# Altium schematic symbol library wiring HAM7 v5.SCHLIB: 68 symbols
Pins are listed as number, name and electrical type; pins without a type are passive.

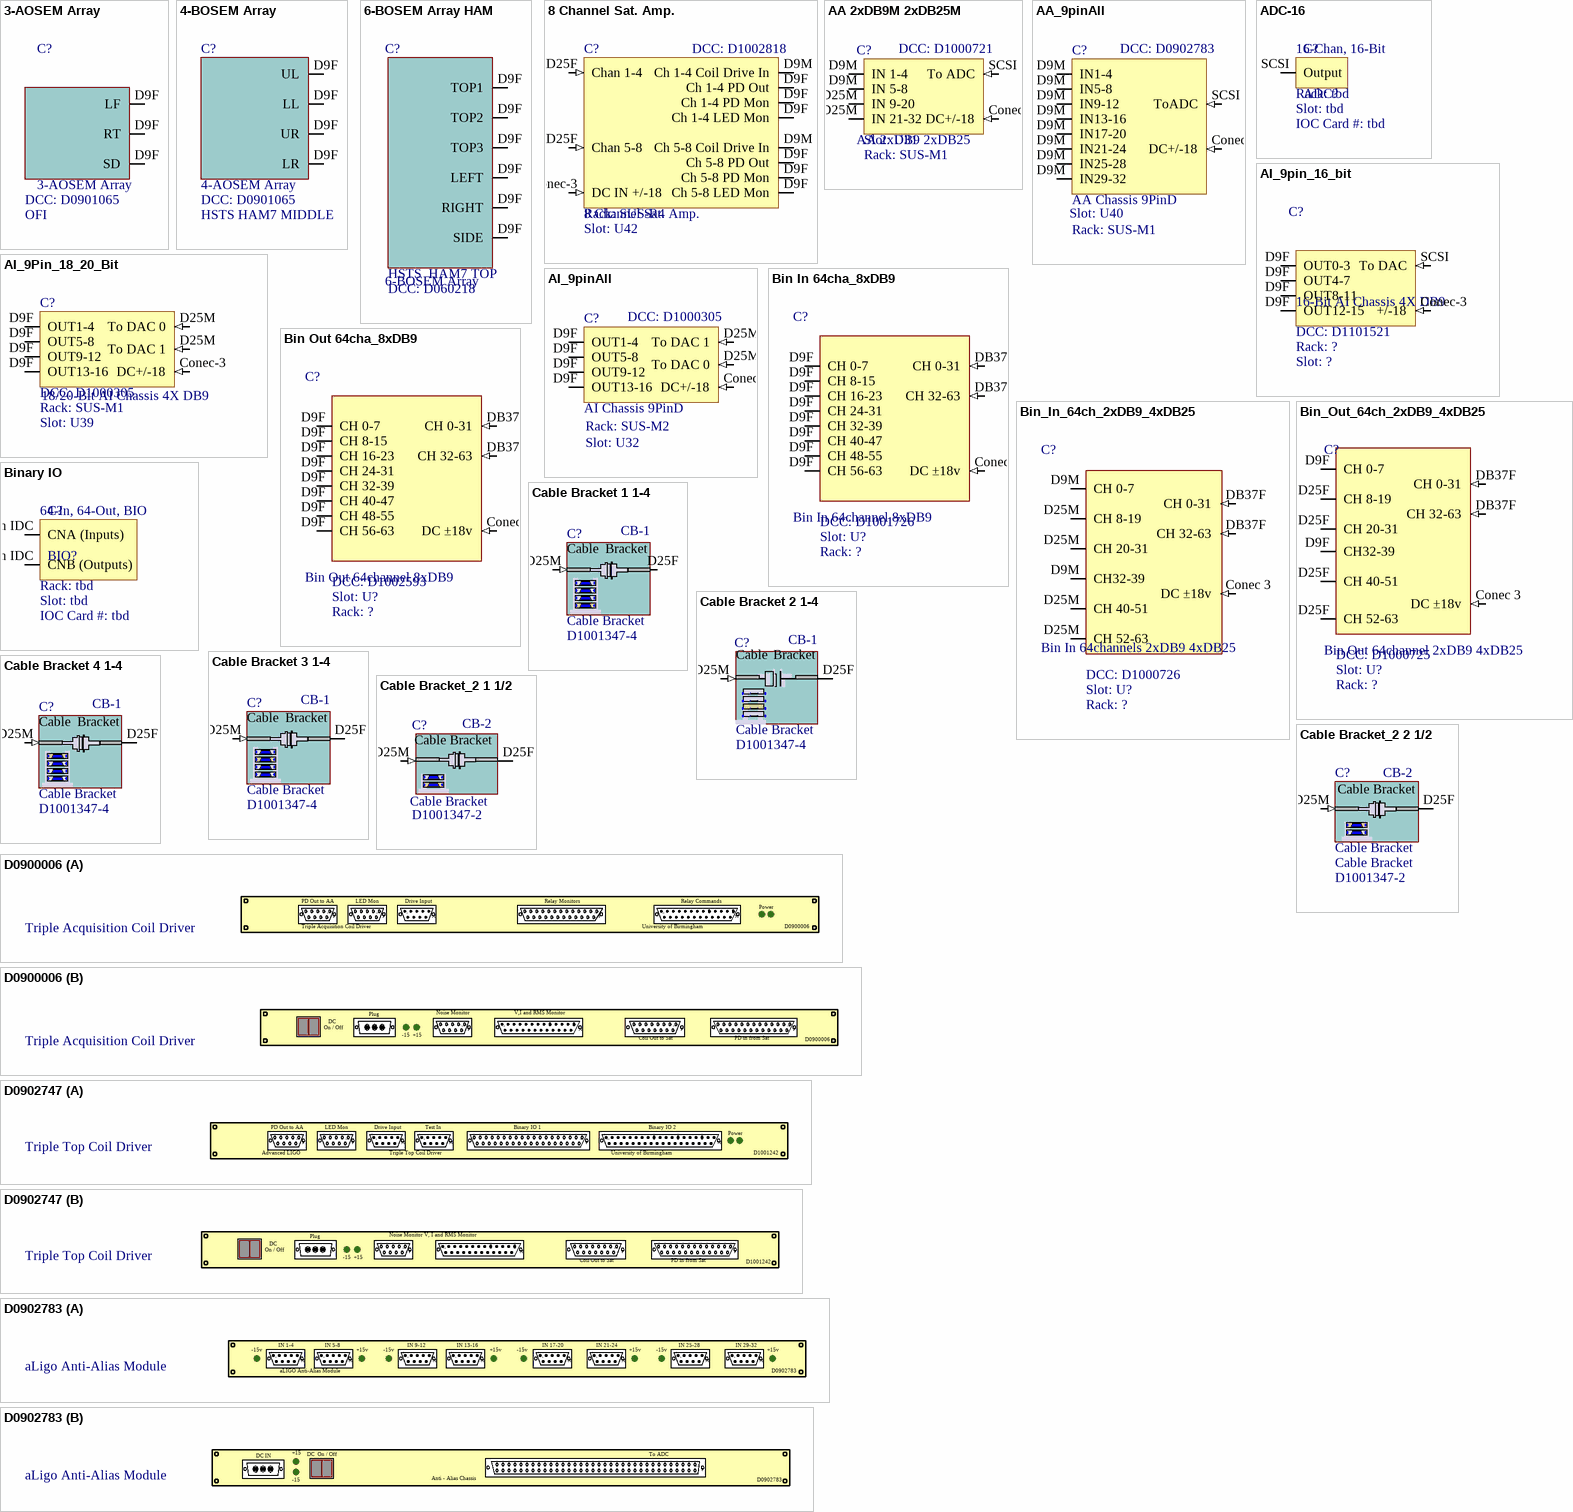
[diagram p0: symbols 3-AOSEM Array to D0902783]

## 3-AOSEM Array
designator C?  DCC: D0901065  Parameter: OFI
Rack: SUS-R?; Serial: Sxxxxxxx; Slot: U?; System: SUS
pins: D9F LF, D9F RT, D9F SD

## 4-BOSEM Array
designator C?, comment 4-AOSEM Array  DCC: D0901065  Parameter: HSTS HAM7 MIDDLE
4-BOSEM Array; Rack: SUS-R?; Serial: Sxxxxxxx; Slot: U?; System: SUS
pins: D9F UL, D9F LL, D9F UR, D9F LR

## 6-BOSEM Array HAM
designator C?, comment 6-BOSEM Array  Parameter 1: HSTS  HAM7 TOP  DCC: D060218
6-BOSEM Array HAM; Serial: Sxxxxxxx; System: SUS; Slot: U?; Rack: SUS-R?
pins: D9F TOP1, D9F TOP2, D9F TOP3, D9F LEFT, D9F RIGHT, D9F SIDE

## 8 Channel Sat. Amp.
designator C?  DCC: D1002818  Rack: SUS-R4  Slot: U42
Serial: Sxxxxxxx; System: ISC
pins: Conec-3 DC IN +/-18 (in), D9F Ch 1-4 PD Out, D9F Ch 1-4 PD Mon, D9F Ch 1-4 LED Mon, D9F Ch 5-8 PD Out, D9F Ch 5-8 PD Mon, D9F Ch 5-8 LED Mon, D9M Ch 1-4 Coil Drive In, D9M Ch 5-8 Coil Drive In, D25F Chan 1-4 (in), D25F Chan 5-8 (in)

## AA 2xDB9M 2xDB25M
designator C?, comment AA 2xDB9 2xDB25  Slot: U31  Rack: SUS-M1  DCC: D1000721
System: SUS; Serial: Sxxxxxxx
pins: Conec-3 DC+/-18 (in), D9M IN 1-4, D9M IN 5-8, D25M IN 9-20, D25M IN 21-32, SCSI 68p To ADC (in)

## AA_9pinAll
designator C?, comment AA Chassis 9PinD  DCC: D0902783  Rack: SUS-M1  Slot: U40
ISC AA Chassis 9PinD; Serial: Sxxxxxxx
pins: Conec-3 DC+/-18 (in), D9M IN1-4, D9M IN5-8, D9M IN9-12, D9M IN13-16, D9M IN17-20, D9M IN21-24, D9M IN25-28, D9M IN29-32, SCSI ToADC (in)

## ADC-16
designator C?, comment ADC?  IOC Card #: tbd
16 Chan, 16 Bit ADC
pins: SCSI Output

## AI_9pin_16_bit
designator C?, comment 16-Bit AI Chassis 4X DB9  DCC: D1101521
AI Chassis 4X DB9 16-bit; Serial: Sxxxxxxx; System: ISC
pins: Conec-3 +/-18 (in), D9F OUT0-3, D9F OUT4-7, D9F OUT8-11, D9F OUT12-15, SCSI To DAC (in)

## AI_9Pin_18_20_Bit
designator C?, comment 18/20-Bit AI Chassis 4X DB9  Rack: SUS-M1  Slot: U39  DCC: D1000305
System: SUS; Serial: Sxxxxxxx
pins: Conec-3 DC+/-18 (in), D9F OUT1-4, D9F OUT5-8, D9F OUT9-12, D9F OUT13-16, D25M To DAC 0 (in), D25M To DAC 1 (in)

## AI_9pinAll
designator C?, comment AI Chassis 9PinD  DCC: D1000305  Rack: SUS-M2  Slot: U32
Serial: Sxxxxxxx; System: ISC
pins: Conec-3 DC+/-18 (in), D9F OUT1-4, D9F OUT5-8, D9F OUT9-12, D9F OUT13-16, D25M To DAC 1 (in), D25M To DAC 0 (in)

## Bin In 64cha_8xDB9
designator C?, comment Bin In 64channel 8xDB9  Slot: U?  DCC: D1001726
Serial: Sxxxxxxx; System: SUS
pins: Conec 3 DC ±18v (in), D9F CH 0-7, D9F CH 8-15, D9F CH 16-23, D9F CH 24-31, D9F CH 32-39, D9F CH 40-47, D9F CH 48-55, D9F CH 56-63, DB37F CH 0-31 (in), DB37F CH 32-63 (in)

## Bin Out 64cha_8xDB9
designator C?, comment Bin Out 64channel 8xDB9  Slot: U?  DCC: D1002593
Serial: Sxxxxxxx; System: SUS
pins: Conec 3 DC ±18v (in), D9F CH 0-7, D9F CH 8-15, D9F CH 16-23, D9F CH 24-31, D9F CH 32-39, D9F CH 40-47, D9F CH 48-55, D9F CH 56-63, DB37F CH 0-31 (in), DB37F CH 32-63 (in)

## Bin_In_64ch_2xDB9_4xDB25
designator C?, comment Bin In 64channels 2xDB9 4xDB25  Slot: U?  DCC: D1000726
Serial: Sxxxxxxx; System: SUS
pins: Conec 3 DC ±18v (in), D9M CH32-39, D9M CH 0-7, D25M CH 20-31, D25M CH 40-51, D25M CH 52-63, D25M CH 8-19, DB37F CH 0-31 (in), DB37F CH 32-63 (in)

## Bin_Out_64ch_2xDB9_4xDB25
designator C?, comment Bin Out 64channel 2xDB9 4xDB25  Slot: U?  DCC: D1000725
Serial: Sxxxxxxx; System: SUS
pins: Conec 3 DC ±18v (in), D9F CH32-39, D9F CH 0-7, D25F CH 20-31, D25F CH 40-51, D25F CH 52-63, D25F CH 8-19, DB37F CH 0-31 (in), DB37F CH 32-63 (in)

## Binary IO
designator C?, comment BIO?  IOC Card #: tbd
128 Chan, Contec DIO-6464L-PE
pins: 100Pin IDC CNA (Inputs), 100Pin IDC CNB (Outputs)

## Cable Bracket 1 1-4
designator C?, comment Slot: CB-1  DCC: D1001347-4  (hidden comment: Cable Bracket)
Rack: SUS-R?; Serial: Sxxxxxxx; System: SUS
pins: D25F, D25M (in)

## Cable Bracket 2 1-4
designator C?, comment Slot: CB-1  DCC: D1001347-4  (hidden comment: Cable Bracket)
Rack: SUS-R?; Serial: Sxxxxxxx; System: SUS
pins: D25F, D25M (in)

## Cable Bracket 3 1-4
designator C?, comment Slot: CB-1  DCC: D1001347-4  (hidden comment: Cable Bracket)
Rack: SUS-R?; Serial: Sxxxxxxx; System: SUS
pins: D25F, D25M (in)

## Cable Bracket 4 1-4
designator C?, comment Slot: CB-1  DCC: D1001347-4  (hidden comment: Cable Bracket)
Rack: SUS-R?; Serial: Sxxxxxxx; System: SUS
pins: D25F, D25M (in)

## Cable Bracket_2 1 1/2
designator C?, comment Slot: CB-2  DCC: D1001347-2  (hidden comment: Cable Bracket)
Rack: SUS-R?; Serial: Sxxxxxxx; System: SUS
pins: D25F, D25M (in)

## Cable Bracket_2 2 1/2
designator C?, comment Cable Bracket  Slot: CB-2  DCC: D1001347-2
Rack: SUS-R?; Serial: Sxxxxxxx; System: SUS
pins: D25F, D25M (in)

## D0900006
designator Chassis28_A?, comment Triple Acquisition Coil Driver

## D0902747
designator Chassis41_A?, comment Triple Top Coil Driver

## D0902783
designator Chassis40_A?, comment aLigo Anti-Alias Module

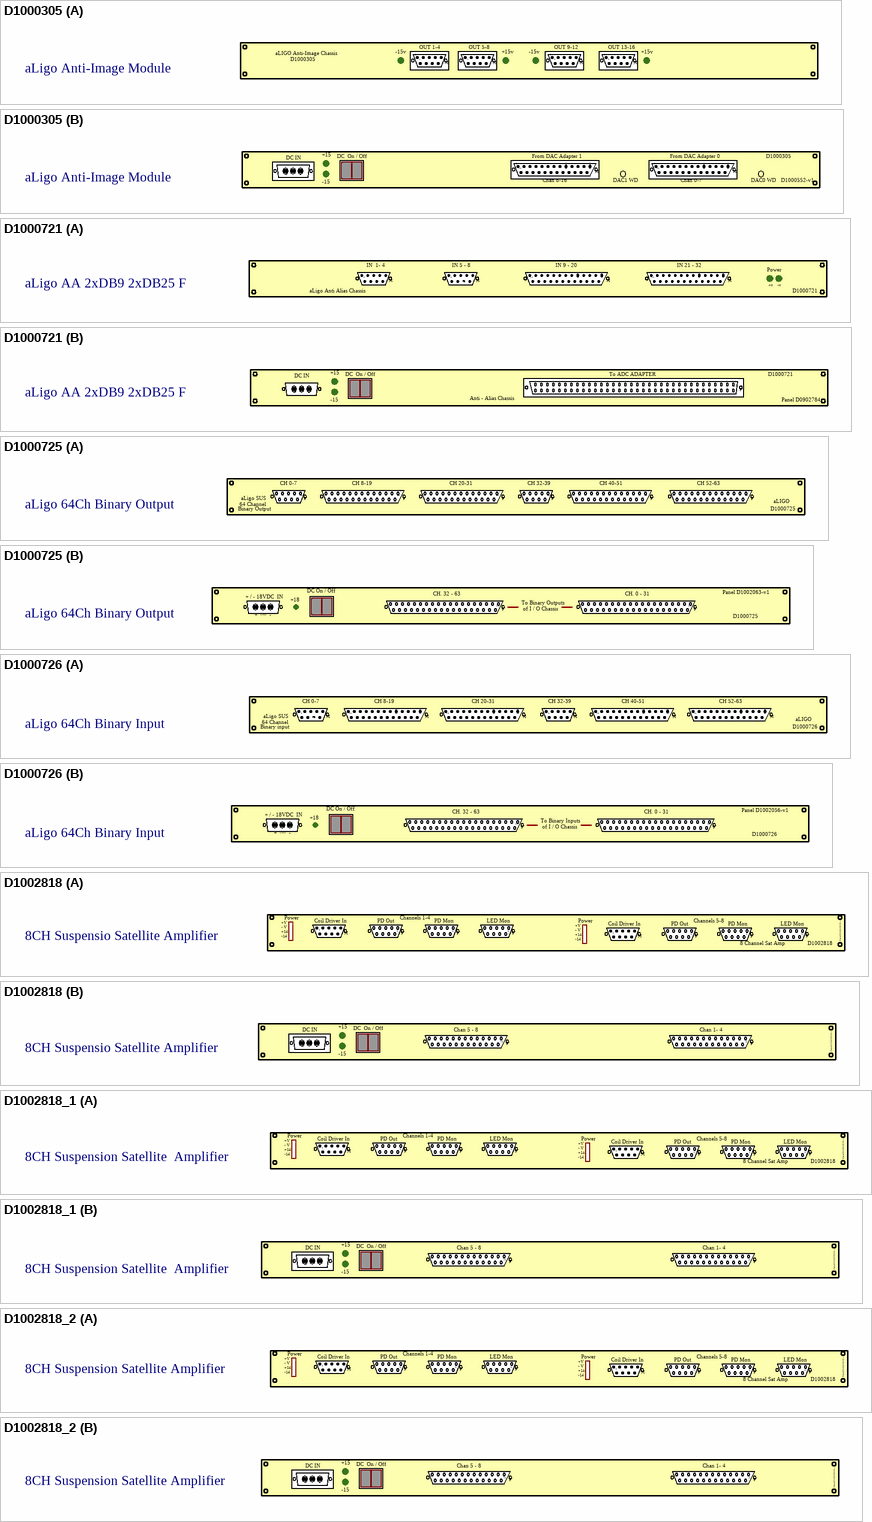
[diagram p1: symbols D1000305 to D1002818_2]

## D1000305
designator Chassis39_B?, comment aLigo Anti-Image Module

## D1000721
designator Chassis38_A?, comment aLigo AA 2xDB9 2xDB25 F

## D1000725
designator Chassis37_A?, comment aLigo 64Ch Binary Output

## D1000726
designator Chassis36_B?, comment aLigo 64Ch Binary Input

## D1002818
designator Chassis42_2A?, comment 8CH Suspensio Satellite Amplifier
8CH Sat Amp

## D1002818_1
designator Chassis36_2A?, comment 8CH Suspension Satellite  Amplifier
8CH Sat Amp

## D1002818_2
designator Chassis29_2A?, comment 8CH Suspension Satellite Amplifier
8CH Sat Amp

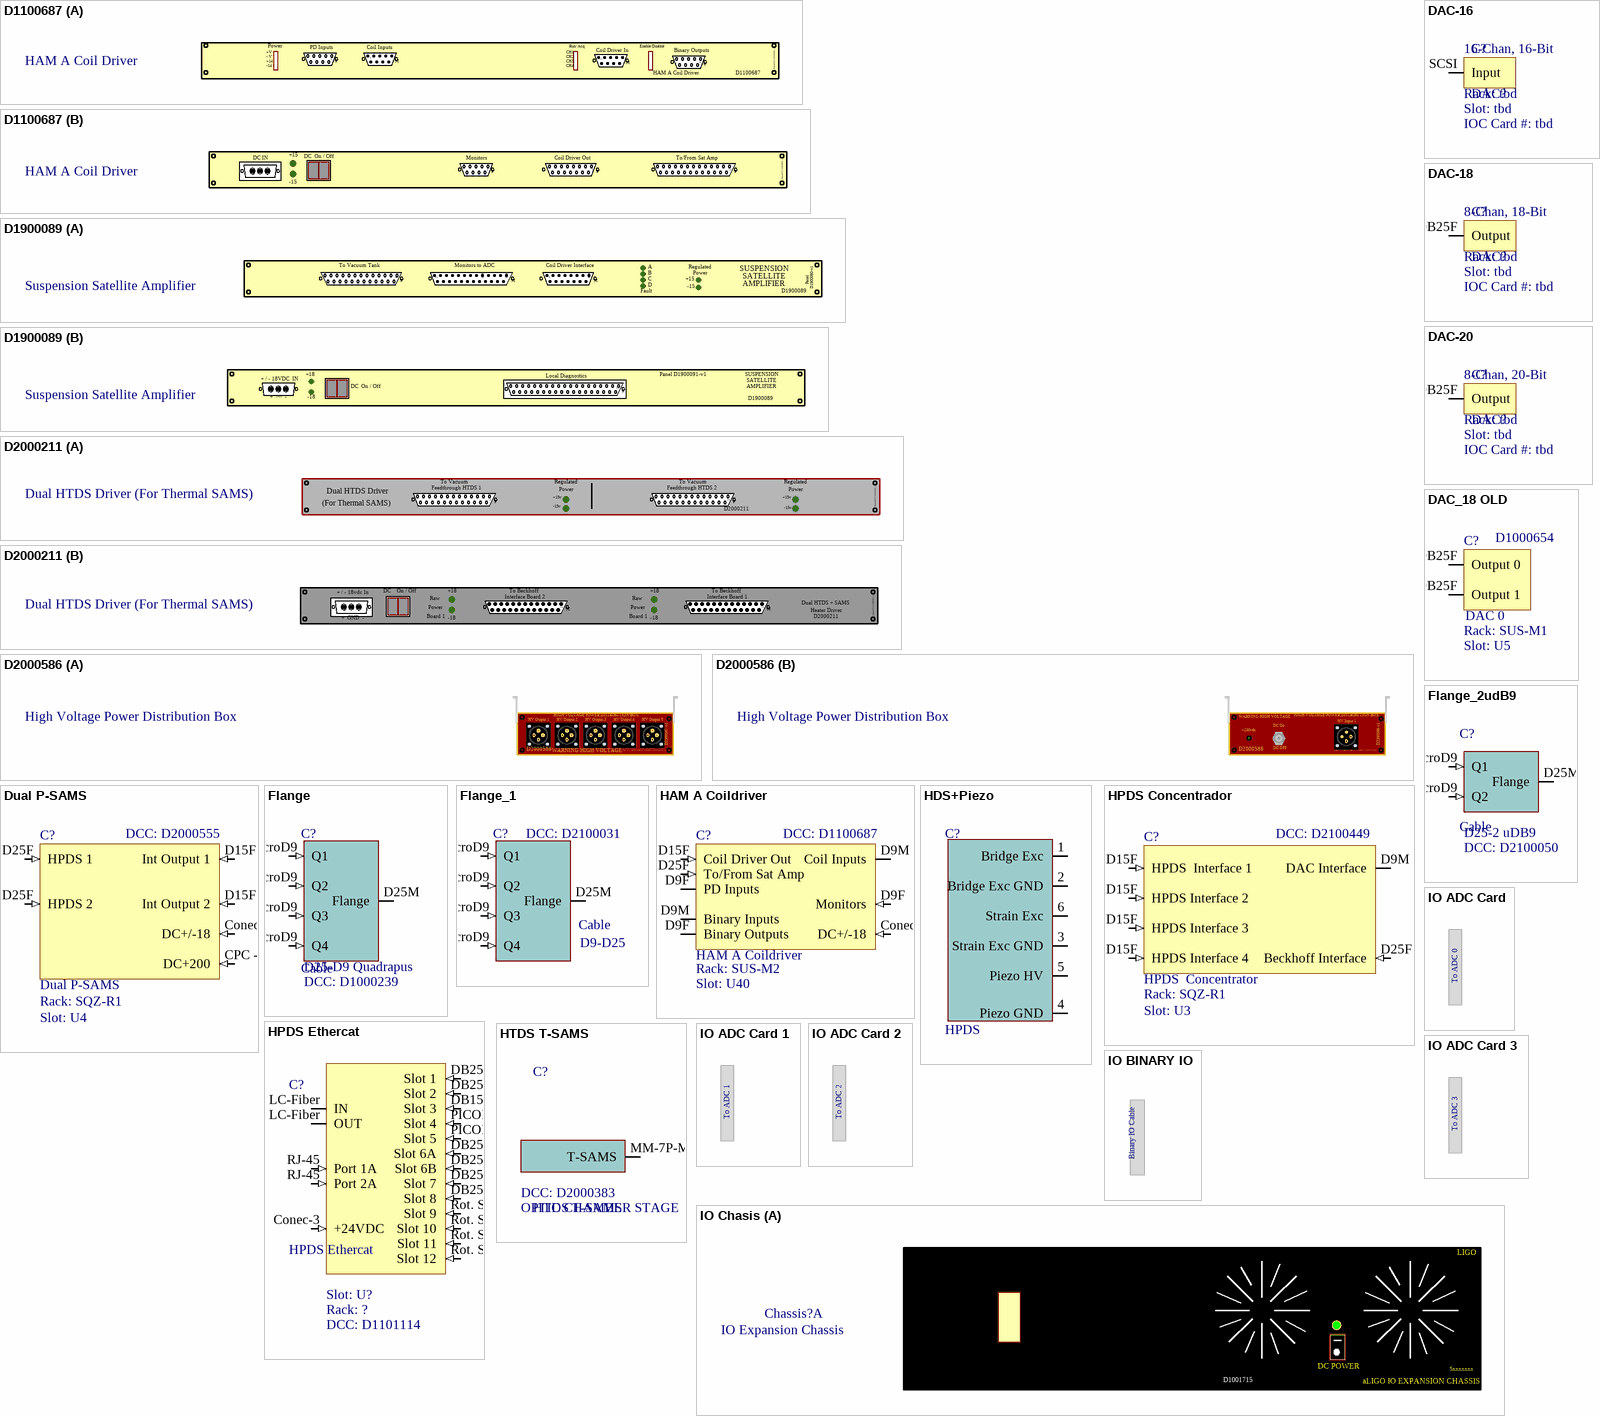
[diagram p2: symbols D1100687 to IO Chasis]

## D1100687
designator Chassis41_2B?, comment HAM A Coil Driver

## D1900089
designator Chassis?, comment Suspension Satellite Amplifier

## D2000211
designator C?, comment Dual HTDS Driver (For Thermal SAMS)

## D2000586
designator C?, comment High Voltage Power Distribution Box

## DAC-16
designator C?, comment DAC?  IOC Card #: tbd
16 Chan, 16 Bit DAC
pins: SCSI Input

## DAC-18
designator C?, comment DAC?  IOC Card #: tbd
8 Chan, 18 Bit DAC
pins: DB25F Output

## DAC-20
designator C?, comment DAC?  IOC Card #: tbd
8 Chan, 20 Bit DAC
pins: DB25F Output

## DAC_18 OLD
designator C?, comment DCC: D1000654  Rack: SUS-M1  Slot: U5  Parameter 1: DAC 0  (hidden comment: 18 Bit DAC)
Serial: Sxxxxxxx; System: ISC
pins: DB25F Output 0, DB25F Output 1

## Dual P-SAMS
designator C?  Slot: U4  Rack: SQZ-R1  DCC: D2000555
Strain Gauge and PZT Driver; Serial: Sxxxxxxx; System: SUS
pins: Conec-3 DC+/-18 (in), CPC - 3 DC+200 (in), D15F Int Output 1 (in), D15F Int Output 2 (in), D25F HPDS 1 (in), D25F HPDS 2 (in)

## Flange
designator C?, comment Cable  value D25-D9 Quadrapus  DCC: D1000239
Rack: SUS-R?; Serial: Sxxxxxxx; Slot: U?; System: SUS
pins: D25M Flange, MicroD9 Q1 (in), MicroD9 Q2 (in), MicroD9 Q3 (in), MicroD9 Q4 (in)

## Flange_1
designator C?, comment Cable  value D9-D25  DCC: D2100031
Rack: SUS-R?; Serial: Sxxxxxxx; Slot: U?; System: SUS
pins: D25M Flange, MicroD9 Q1 (in), MicroD9 Q2 (in), MicroD9 Q3 (in), MicroD9 Q4 (in)

## Flange_2udB9
designator C?, comment Cable  value D25-2 uDB9  DCC: D2100050
Rack: SUS-R?; Serial: Sxxxxxxx; Slot: U?; System: SUS
pins: D25M Flange, MicroD9 Q1 (in), MicroD9 Q2 (in)

## HAM A Coildriver
designator C?  DCC: D1100687  Rack: SUS-M2  Slot: U40
Serial: Sxxxxxxx; System: ISC
pins: Conec-3 DC+/-18 (in), D9F PD Inputs, D9F Monitors (in), D9F Binary Outputs, D9M Coil Inputs, D9M Binary Inputs, D15F Coil Driver Out (in), D25F To/From Sat Amp (in)

## HDS+Piezo
designator C?, comment HPDS
HAM Double Suspension with Piezo Driver
pins: 1 Bridge Exc, 2 Bridge Exc GND, 3 Strain Exc GND, 4 Piezo GND, 5 Piezo HV, 6 Strain Exc

## HPDS Concentrador
designator C?, comment HPDS  Concentrator  Slot: U3  Rack: SQZ-R1  DCC: D2100449
HPDS  Concentrador; Serial: S?; System: SUS
pins: D9M DAC Interface, D15F HPDS  Interface 1 (in), D15F HPDS Interface 2 (in), D15F HPDS Interface 3 (in), D15F HPDS Interface 4 (in), D25F Beckhoff Interface (in)

## HPDS Ethercat
designator C?  Slot: U?  DCC: D1101114
PSL - C1; System: ISC; Serial: Sxxxxxxx
pins: Conec-3 +24VDC (in), DB15M Slot 3 (in), DB25F Slot 1 (in), DB25F Slot 2 (in), DB25F Slot 6A (in), DB25F Slot 6B (in), DB25M Slot 8 (in), DB25M Slot 7 (in), LC-Fiber IN, LC-Fiber OUT, PICOMOTOR Slot 4 (in), PICOMOTOR Slot 5 (in), RJ-45 Port 1A (in), RJ-45 Port 2A (in), Rot. Stage Slot 9 (in), Rot. Stage Slot 10 (in), Rot. Stage Slot 11 (in), Rot. Stage Slot 12 (in)

## HTDS T-SAMS
designator C?  DCC: D2000383  Location: OPTIC CHAMBER STAGE
Heater and two thermistors; Rack: SUS-R?; Serial: Sxxxxxxx; Slot: U?; System: SUS
pins: MM-7P-M T-SAMS

## IO ADC Card
designator ADC?, comment ADC0  (value not drawn)

## IO ADC Card 1
designator ADC?, comment ADC1  (value not drawn)

## IO ADC Card 2
designator ADC?, comment ADC2  (value not drawn)

## IO ADC Card 3
designator ADC?, comment ADC3  (value not drawn)

## IO BINARY IO
designator Binary IO?, comment Binary IO  (value not drawn)

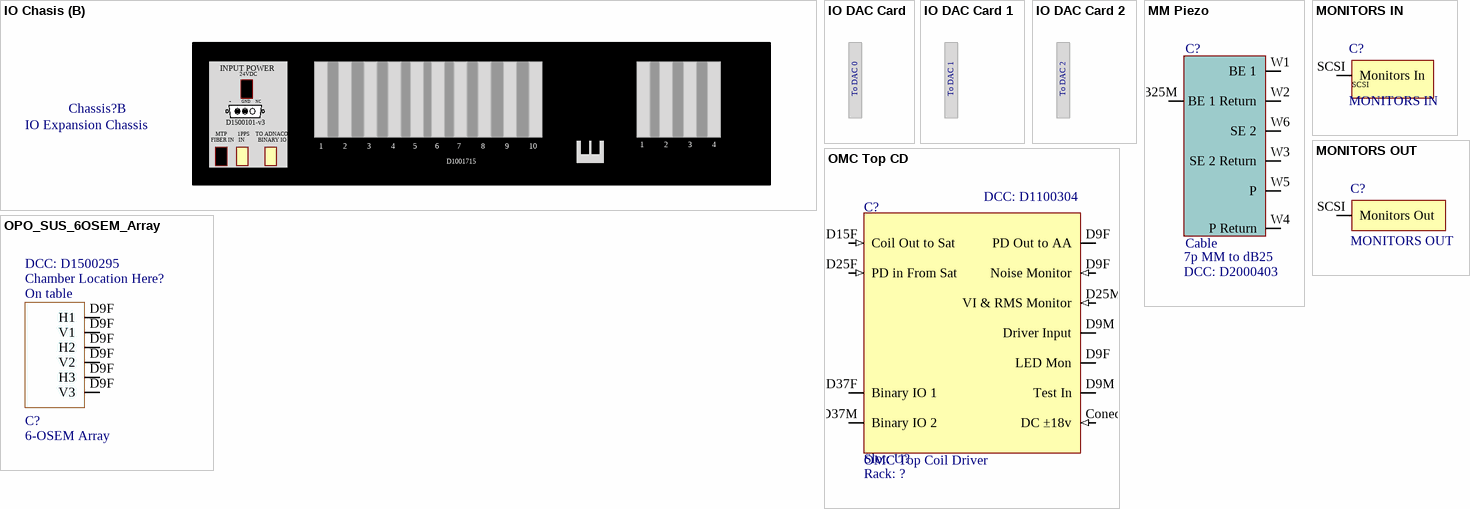
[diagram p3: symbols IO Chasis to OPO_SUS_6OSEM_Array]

## IO Chasis
designator Chassis?, comment IO Expansion Chassis

## IO DAC Card
designator DAC?, comment DAC0  (value not drawn)

## IO DAC Card 1
designator DAC?, comment DAC1  (value not drawn)

## IO DAC Card 2
designator DAC?, comment DAC2  (value not drawn)

## MM Piezo
designator C?, comment Cable  value 7p MM to dB25  DCC: D2000403
Piezo or Thermal; Rack: SUS-R?; Serial: Sxxxxxxx; Slot?: U?; System: SUS
pins: DB25M 7, W1 BE 1, W2 BE 1 Return, W3 SE 2 Return, W4 P Return, W5 P, W6 SE 2

## MONITORS IN
designator C?
DCC: tbd; Rack: SUS-R?; Slot: U?; Serial: Sxxxxxxx; System: SUS
pins: SCSI Monitors In

## MONITORS OUT
designator C?
DCC: tdb; Rack: SUS-R?; Slot: U?; Serial: Sxxxxxxx; System: SUS
pins: SCSI Monitors Out

## OMC Top CD
designator C?, comment OMC Top Coil Driver  Slot: U?  DCC: D1100304
System: SUS; Serial: Sxxxxxxx
pins: Conec 3 DC ±18v (in), D9F PD Out to AA, D9F LED Mon, D9F Noise Monitor (in), D9M Test In, D9M Driver Input, D15F Coil Out to Sat (in), D25F PD in From Sat (in), D25M VI & RMS Monitor (in), D37F Binary IO 1, D37M Binary IO 2

## OPO_SUS_6OSEM_Array
designator C?, comment 6-OSEM Array  DCC: D1500295  Rack: Chamber Location Here?  Slot: On table
OPO Suspended Platform OSEM Array
pins: D9F H1, D9F H2, D9F V1, D9F H3, D9F V2, D9F V3

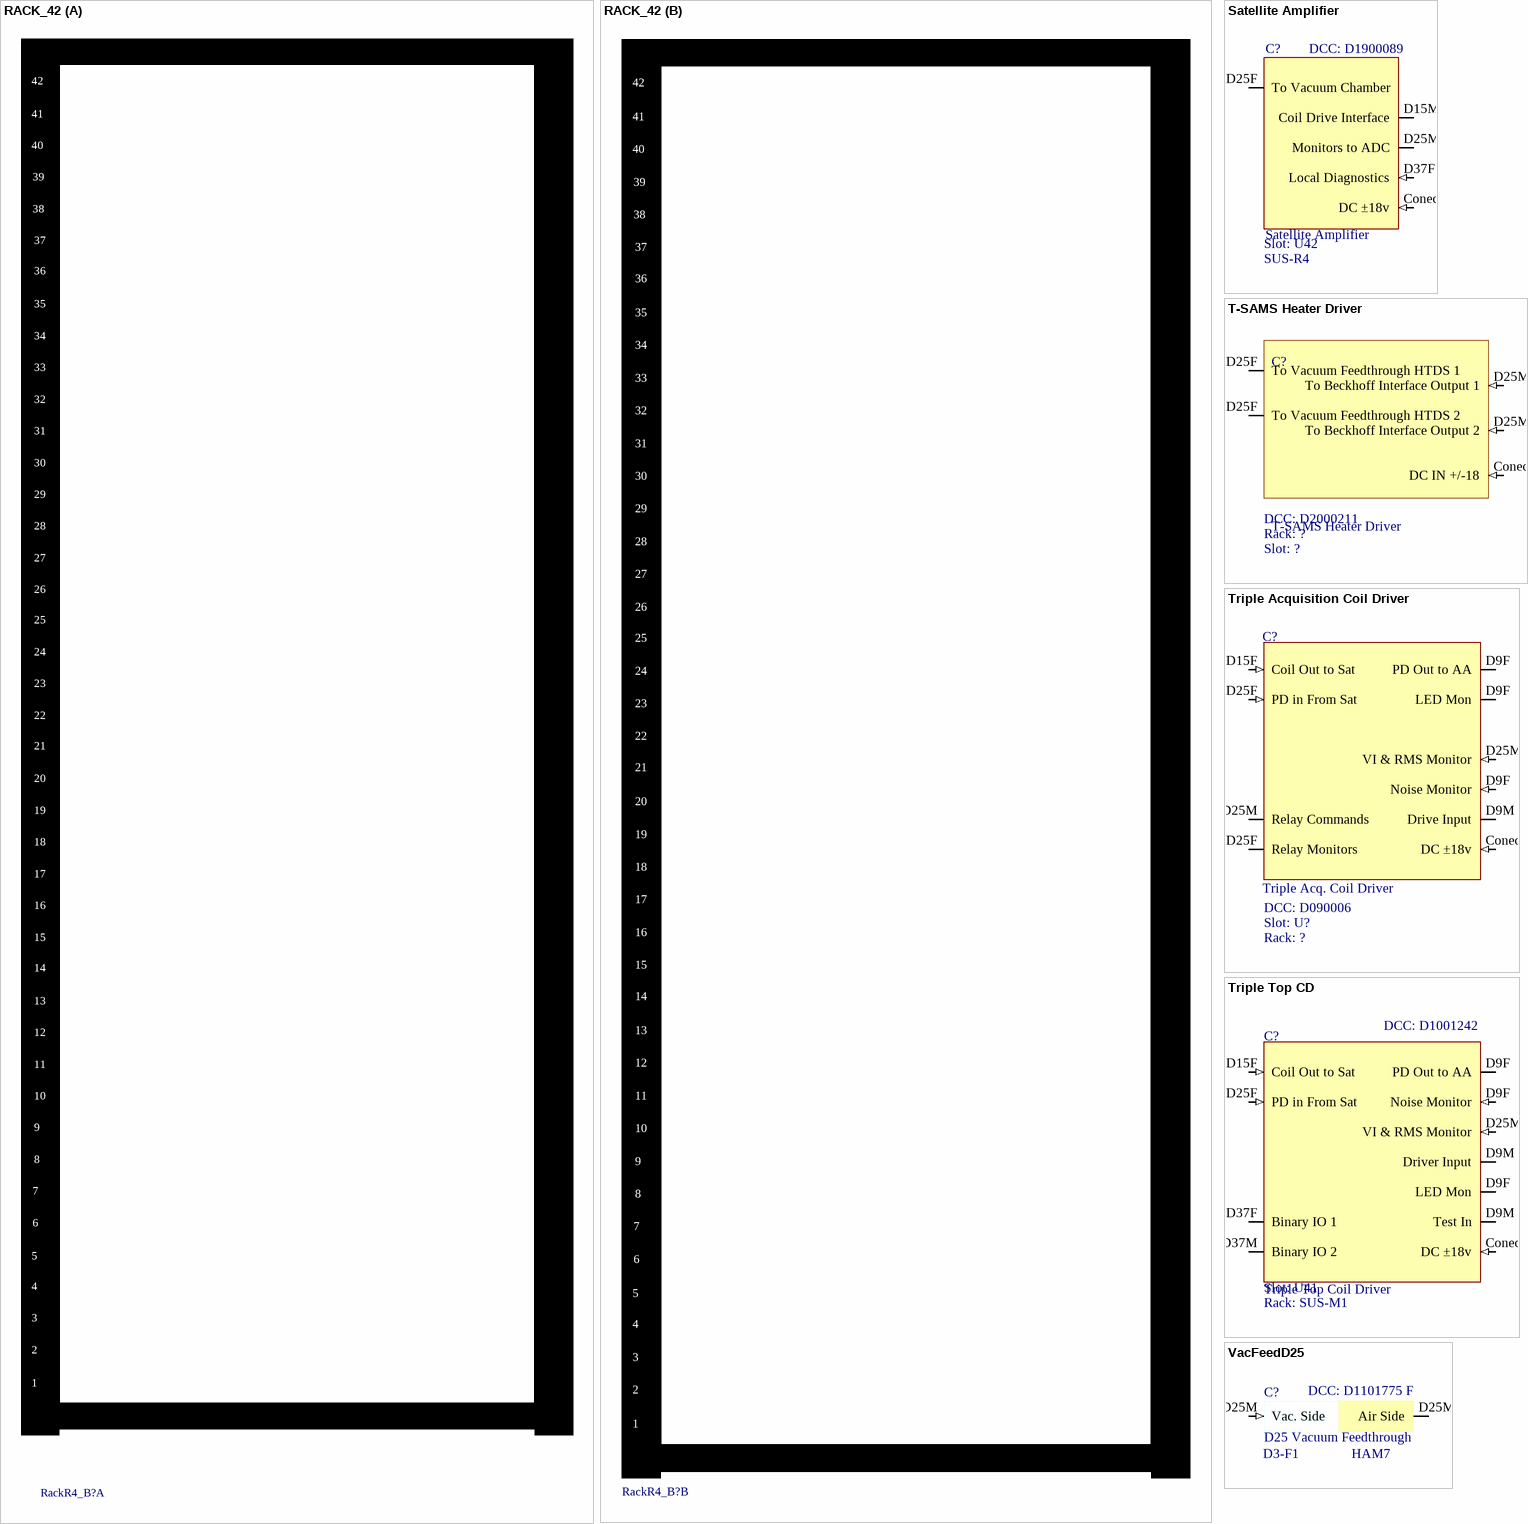
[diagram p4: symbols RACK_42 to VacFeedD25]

## RACK_42
designator RackR4_B?, comment 1U  Rack 42 pos  (value not drawn)

## Satellite Amplifier
designator C?  Slot: U42  Rack: SUS-R4  DCC: D1900089
System: SUS; Serial: Sxxxxxxx
pins: Conec 3 DC ±18v (in), D15M Coil Drive Interface, D25F To Vacuum Chamber, D25M Monitors to ADC, D37F Local Diagnostics (in)

## T-SAMS Heater Driver
designator C?  DCC: D2000211
Serial: Sxxxxxxx
pins: Conec-3 DC IN +/-18 (in), D25F To Vacuum Feedthrough HTDS 1, D25F To Vacuum Feedthrough HTDS 2, D25M To Beckhoff Interface Output 1 (in), D25M To Beckhoff Interface Output 2 (in)

## Triple Acquisition Coil Driver
designator C?, comment Triple Acq. Coil Driver  Slot: U?  DCC: D090006
System: SUS; Serial: Sxxxxxxx
pins: Conec 3 DC ±18v (in), D9F PD Out to AA, D9F LED Mon, D9F Noise Monitor (in), D9M Drive Input, D15F Coil Out to Sat (in), D25F Relay Monitors, D25F PD in From Sat (in), D25M Relay Commands, D25M VI & RMS Monitor (in)

## Triple Top CD
designator C?, comment Triple Top Coil Driver  Slot: U41  Rack: SUS-M1  DCC: D1001242
System: SUS; Serial: Sxxxxxxx
pins: Conec 3 DC ±18v (in), D9F PD Out to AA, D9F LED Mon, D9F Noise Monitor (in), D9M Test In, D9M Driver Input, D15F Coil Out to Sat (in), D25F PD in From Sat (in), D25M VI & RMS Monitor (in), D37F Binary IO 1, D37M Binary IO 2

## VacFeedD25
designator C?, comment D25 Vacuum Feedthrough  DCC: D1101775 F  Feedthrough: D3-F1  Chamber: HAM7
Serial: Sxxxxxxx; System: ISC; Rack: R?; Slot: U?
pins: D25M Vac. Side (in), D25M Air Side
